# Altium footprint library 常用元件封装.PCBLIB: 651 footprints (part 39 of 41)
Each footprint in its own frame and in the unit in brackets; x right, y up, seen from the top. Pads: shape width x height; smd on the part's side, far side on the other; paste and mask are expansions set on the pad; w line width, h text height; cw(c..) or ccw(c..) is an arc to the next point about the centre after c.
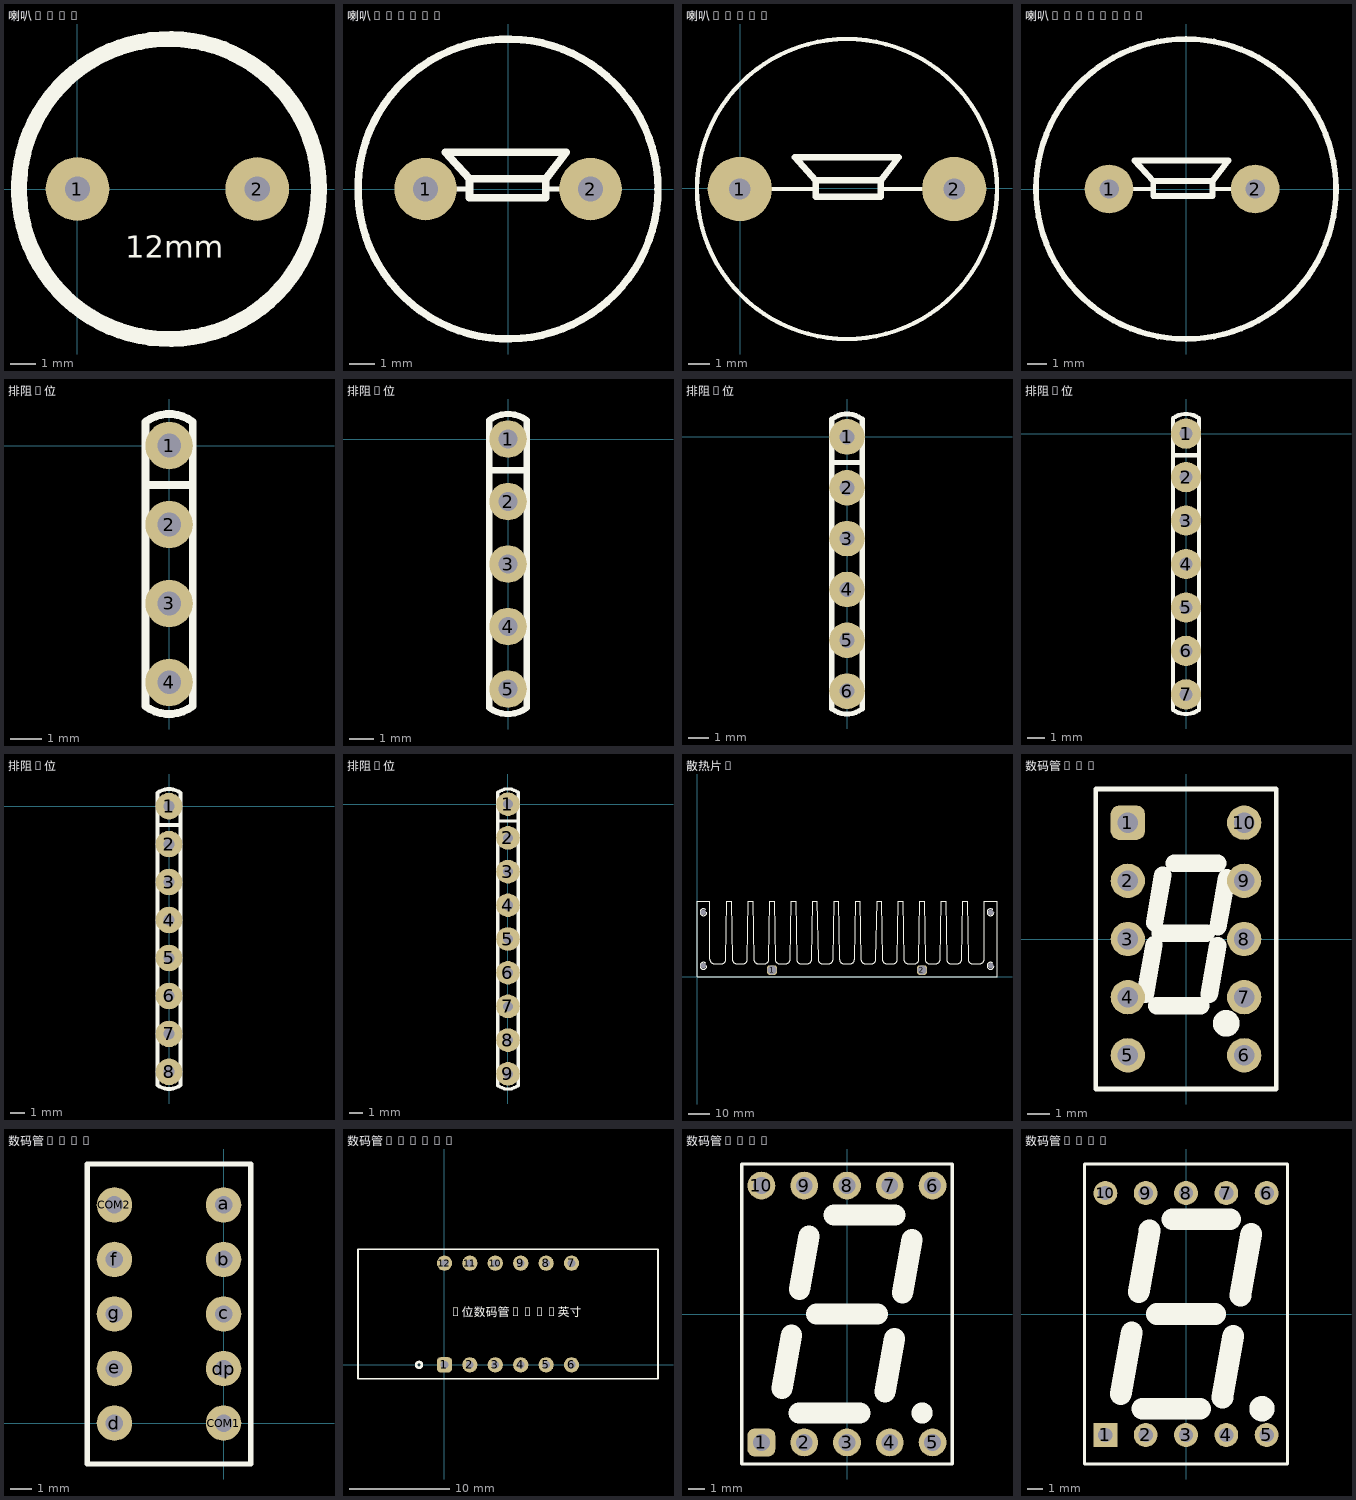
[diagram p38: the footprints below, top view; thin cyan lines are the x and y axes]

## 喇叭12MM [mil] "10.16MM"
pads (2):
  round 100 hole 40: 1(0,0) 2(282.84,0)
TopOverlay:
  circle w25: c144,0 r236
  text "12mm" at 75,-120 h60

## 喇叭12X6.6 [mm]
pads (2):
  round 2.5 hole 1: 1(-3.3,0) 2(3.3,0)
TopOverlay:
  circle w0.3: c0,0 r6
  lines w0.2: -3.3,0 -1.54,0 ; 1.509,0 3.3,0
  lines w0.305: -1.54,0.406 -1.54,-0.356 1.508,-0.356 1.508,0.406 ; -1.54,0.406 1.508,0.406 ; -1.54,0.406 -2.506,1.473 2.328,1.473 1.508,0.406
BottomOverlay:
  lines w0.2: -1.925,0 -1.542,0 ; 1.506,0 1.925,0
  lines w0.305: -1.542,0.405 -2.508,1.471 2.373,1.471 1.506,0.405 ; -1.542,0.405 -1.542,-0.357 1.506,-0.357 1.506,0.405 ; -1.542,0.405 1.506,0.405

## 喇叭14X10 [mm]
pads (2):
  round 3 hole 1: 1(-0.024,-0.025) 2(9.976,-0.025)
TopOverlay:
  circle w0.2: c4.976,-0.025 r7
  lines w0.2: -0.024,-0.025 3.511,-0.025 ; 6.559,-0.025 9.976,-0.025
  lines w0.305: 3.511,0.381 2.544,1.448 7.379,1.448 6.559,0.381 ; 3.511,0.381 6.559,0.381 ; 3.511,0.381 3.511,-0.381 6.559,-0.381 6.559,0.381
BottomOverlay:
  lines w0.2: 1.701,-0.025 3.509,-0.025 ; 6.557,-0.025 8.201,-0.025
  lines w0.305: 3.509,0.379 6.557,0.379 ; 3.509,0.379 3.509,-0.383 6.557,-0.383 6.557,0.379 ; 3.509,0.379 2.542,1.446 7.424,1.446 6.557,0.379

## 喇叭15.4X7.5 [mm]
pads (2):
  round 2.5 hole 1: 1(-3.95,0) 2(3.55,0)
TopOverlay:
  circle w0.3: c0,0 r7.7
  lines w0.2: -3.95,0 -1.682,0 ; 1.367,0 3.55,0
  lines w0.305: -1.682,0.406 -2.648,1.473 2.186,1.473 1.366,0.406 ; -1.682,0.406 1.366,0.406 ; -1.682,0.406 -1.682,-0.356 1.366,-0.356 1.366,0.406
BottomOverlay:
  lines w0.2: -2.575,0 -1.684,0 ; 1.364,0 2.2,0
  lines w0.305: -1.684,0.405 1.364,0.405 ; -1.684,0.405 -1.684,-0.357 1.364,-0.357 1.364,0.405 ; -1.684,0.405 -2.65,1.471 2.231,1.471 1.364,0.405

## 排阻3位 [mil]
height 236.22
pads (4):
  round 60 hole 30: 1(0,0) 2(0,-100) 3(0,-200) 4(0,-300)
TopOverlay:
  lines w10: -30.3,-330 ccw(c-0.15,-289.8) 30,-330 30,30 ccw(c0,-10) -30,30 -30,-330 ; -30,-50 30,-50

## 排阻4位 [mil]
height 236.22
pads (5):
  round 60 hole 30: 1(0,0) 2(0,-100) 3(0,-200) 4(0,-300) 5(0,-400)
TopOverlay:
  lines w10: -30,-50 30,-50 ; -30,-430 ccw(c0,-390) 30,-430 30,30 ccw(c0,-10) -30,30 -30,-430

## 排阻5位 [mil]
height 236.22
pads (6):
  round 70 hole 30: 1(0,0) 2(0,-100) 3(0,-200) 4(0,-300) 5(0,-400) 6(0,-500)
TopOverlay:
  lines w10: -30,-50 30,-50 ; -30,-535 ccw(c0,-495) 30,-535 30,35 ccw(c0,-5) -30,35 -30,-535

## 排阻6位 [mil]
height 236.22
pads (7):
  round 70 hole 30: 1(0,0) 2(0,-100) 3(0,-200) 4(0,-300) 5(0,-400) 6(0,-500) 7(0,-600)
TopOverlay:
  lines w10: -30,-50 30,-50 ; -30,-635 ccw(c0,-595) 30,-635 30,35 ccw(c0,-5) -30,35 -30,-635

## 排阻7位 [mil]
height 236.22
pads (8):
  round 70 hole 30: 1(0,0) 2(0,-100) 3(0,-200) 4(0,-300) 5(0,-400) 6(0,-500) 7(0,-600) 8(0,-700)
TopOverlay:
  lines w10: -30,-50 30,-50 ; -30,-735 ccw(c0,-695) 30,-735 30,35 ccw(c0,-5) -30,35 -30,-735

## 排阻8位 [mil]
height 236.22
pads (9):
  round 70 hole 30: 1(0,0) 2(0,-100) 3(0,-200) 4(0,-300) 5(0,-400) 6(0,-500) 7(0,-600) 8(0,-700) 9(0,-800)
TopOverlay:
  lines w10: -30,-50 30,-50 ; -30,-835 ccw(c0,-795) 30,-835 30,35 ccw(c0,-5) -30,35 -30,-835

## 散热片1 [mm] "140mmX35mm"
pads (6):
  round 2 hole 2.5: 0(3,5) 0(3,30) 0(137,5) 0(137,30)
  rrect50% 4.5x4.5 hole 4.2: 1(35,3) 2(105,3)
TopOverlay:
  lines w0.229: 4.131,6.131 ccw(c3,5) 4.6,5 ; 4.131,31.131 ccw(c3,30) 4.6,30 ; 138.131,6.131 ccw(c137,5) 138.6,5 ; 138.131,31.131 ccw(c137,30) 138.6,30
  lines w0.254: 18,6 21.5,6 ccw(c21.5,8) 23.5,8 24,35 26,35 26.5,8 ccw(c28.5,8) 28.5,6 ; 18.5,6 cw(c18.5,8) 16.5,8 16,35 14,35 13.5,8 cw(c11.5,8) 11.5,6 8,6 cw(c8,8) 6,8 6,35 0,35 0,0 140,0 140,35 ; 28,6 31.5,6 ccw(c31.5,8) 33.5,8 34,35 36,35 36.5,8 ccw(c38.5,8) 38.5,6 ; 38,6 41.5,6 ccw(c41.5,8) 43.5,8 44,35 46,35 46.5,8 ccw(c48.5,8) 48.5,6 ; 48,6 51.5,6 ccw(c51.5,8) 53.5,8 54,35 56,35 56.5,8 ccw(c58.5,8) 58.5,6 ; 58,6 61.5,6 ccw(c61.5,8) 63.5,8 64,35 66,35 66.5,8 ccw(c68.5,8) 68.5,6 ; 68,6 71.5,6 ccw(c71.5,8) 73.5,8 74,35 76,35 76.5,8 ccw(c78.5,8) 78.5,6 ; 78,6 81.5,6 ccw(c81.5,8) 83.5,8 84,35 86,35 86.5,8 ccw(c88.5,8) 88.5,6 ; 88,6 91.5,6 ccw(c91.5,8) 93.5,8 94,35 96,35 96.5,8 ccw(c98.5,8) 98.5,6 ; 98,6 101.5,6 ccw(c101.5,8) 103.5,8 104,35 106,35 106.5,8 ccw(c108.5,8) 108.5,6 ; 108,6 111.5,6 ccw(c111.5,8) 113.5,8 114,35 116,35 116.5,8 ccw(c118.5,8) 118.5,6 ; 118,6 121.5,6 ccw(c121.5,8) 123.5,8 124,35 126,35 126.5,8 ccw(c128.5,8) 128.5,6 ; 128,6 132,6 ccw(c132,8) 134,8 134,35 ; 134,35 140,35 ; 134,35 140,35

## 数码管0.3 [mm] "LED, 7-Segment Display, 7.62 mm, RHD; 10 Leads; Row Space 5.08 mm; Pitch 2.54 mm"
height 6.34
pads (10):
  rrect50% 1.5x1.5 hole 0.9: 1(-2.54,5.08)
  round 1.5 hole 0.9: 2(-2.54,2.54) 3(-2.54,0) 4(-2.54,-2.54) 5(-2.54,-5.08) 6(2.54,-5.08) 7(2.54,-2.54) 8(2.54,0) 9(2.54,2.54) 10(2.54,5.08)
TopOverlay:
  circle w0.86: c1.755,-3.683 r0.15
  lines w0.2: -3.95,-6.55 3.95,-6.55 3.95,6.55 -3.95,6.55 -3.95,-6.55
  lines w0.762: -1.777,-2.424 -1.397,-0.254 ; -1.376,0.714 -1.016,2.794 ; -1.285,-2.921 0.635,-2.921 ; -1.119,0.254 0.889,0.254 ; -0.508,3.302 1.382,3.302 ; 1.016,-2.413 1.386,-0.283 ; 1.398,0.537 1.778,2.667

## 数码管0.36 [mil]
pads (10):
  round 65 hole 32: a(0,400) b(0,300) c(0,200) COM1(0,0) COM2(-200,400) d(-200,0) dp(0,100) e(-200,100) f(-200,300) g(-200,200)
TopOverlay:
  lines w10: -250,-75 50,-75 50,475 -250,475 -250,-75

## 数码管0.36/4 [mil] "30mmX14.0mm"
height 283.46
pads (12):
  rrect50% 60x60 hole 30: 1(0,0)
  round 60 hole 30: 2(100,0) 3(200,0) 4(300,0) 5(400,0) 6(500,0) 7(500,400) 8(400,400) 9(300,400) 10(200,400) 11(100,400) 12(0,400)
TopOverlay:
  circle w10: c-100,0 r11.18
  lines w6.69: -340,-55 -340,455 840,455 840,-55 -340,-55
  text "4位数码管0.36英寸" at 20,180 h60

## 数码管0.52 [mm] "LED, 7-Segment Display, 13 mm, RHD; 10 Leads; Row Space 15.24 mm; Pitch 2.54 mm"
height 7.25
pads (10):
  rrect50% 1.65x1.65 hole 1: 1(-5.08,-7.62)
  round 1.65 hole 1: 2(-2.54,-7.62) 3(0,-7.62) 4(2.54,-7.62) 5(5.08,-7.62) 6(5.08,7.62) 7(2.54,7.62) 8(0,7.62) 9(-2.54,7.62) 10(-5.08,7.62)
TopOverlay:
  circle w0.85: c4.455,-5.872 r0.2
  lines w0.2: -6.25,-8.9 6.25,-8.9 6.25,8.9 -6.25,8.9 -6.25,-8.9
  lines w1.25: -3.857,-4.427 -3.295,-1.251 ; -2.84,-5.875 0.756,-5.875 ; -2.818,1.449 -2.257,4.627 ; -1.802,0 1.802,0 ; -0.767,5.875 2.837,5.875 ; 2.26,-4.624 2.818,-1.45 ; 3.295,1.25 3.854,4.424

## 数码管0.56 [mm] "LED, 7-Segment Display, 14.2 mm, RHD; 10 Leads; Row Space 15.24 mm; Pitch 2.54 mm"
height 8.25
pads (10):
  rect 1.5x1.5 hole 0.9: 1(-5.08,-7.62)
  round 1.5 hole 0.9: 2(-2.54,-7.62) 3(0,-7.62) 4(2.54,-7.62) 5(5.08,-7.62) 6(5.08,7.62) 7(2.54,7.62) 8(0,7.62) 9(-2.54,7.62) 10(-5.08,7.62)
TopOverlay:
  circle w1: c4.784,-5.969 r0.296
  lines w0.2: -6.4,-9.45 -6.4,9.45 6.4,9.45 6.4,-9.45 -6.4,-9.45
  lines w1.37: -4.108,-5.054 -3.425,-1.17 ; -2.974,1.368 -2.293,5.255 ; -2.761,-5.972 0.889,-5.969 ; -1.821,0 1.828,0 ; -0.855,5.969 2.794,5.969 ; 2.295,-5.256 2.98,-1.371 ; 3.427,1.169 4.11,5.058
